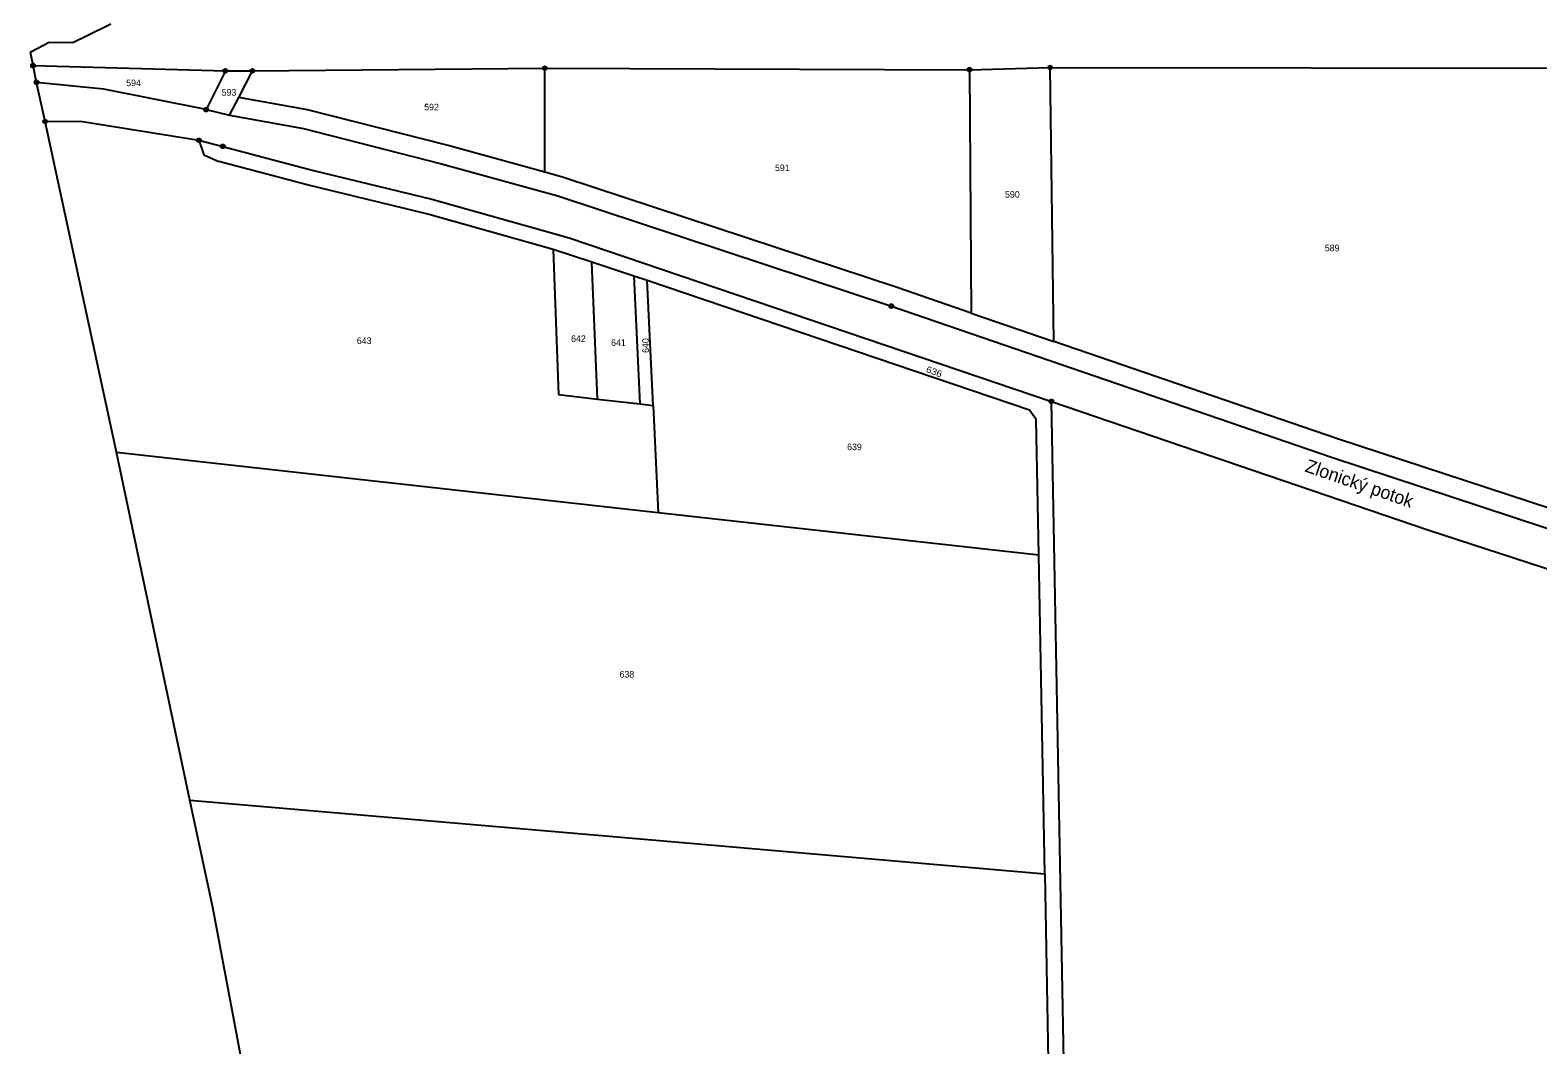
# Model space of a CAD drawing. Extents: x -759947 to -757003, y -1019641 to -1017100.
# Drawn here: x -759814.7 to -759425.7, y -1018690.8 to -1018428.9 of the extents above; entities that cross this region are included whole.
import ezdxf
from ezdxf.enums import TextEntityAlignment as Align

# ---------------------------------------------------------------- set-up
doc = ezdxf.new("R2010")
doc.units = 0
doc.header["$LTSCALE"] = 0.68
for name, color, linetype, lineweight in [('1', 7, 'Continuous', 25), ('7', 7, 'Continuous', 13), ('8', 7, 'Continuous', 25)]:
    doc.layers.add(name, color=color, linetype=linetype, lineweight=lineweight)
doc.layers.add('2', color=7, linetype='Continuous')

msp = doc.modelspace()

# ---------------------------------------------------------------- linework, layer by layer
at = {"layer": '1'}
for p, q in [((-759793.9, -1018427.43), (-759800.17, -1018430.47)), ((-759800.17, -1018430.47), (-759803.53, -1018432.1)), ((-759814.67, -1018434.67), (-759809.76, -1018432.02)), ((-759814.67, -1018434.67), (-759814.33, -1018436.27)), ((-759809.76, -1018432.02), (-759803.53, -1018432.1)), ((-759814.33, -1018436.27), (-759813.93, -1018438.11)), ((-759813, -1018442.42), (-759813.93, -1018438.11)), ((-759813.93, -1018438.11), (-759764.32, -1018439.44)), ((-759757.31, -1018439.44), (-759681.89, -1018438.78)), ((-759681.87, -1018465.61), (-759681.89, -1018438.78)), ((-759681.89, -1018438.78), (-759572.38, -1018439.15)), ((-759572.38, -1018439.15), (-759551.55, -1018438.58)), ((-759572.38, -1018439.15), (-759571.91, -1018501.94)), ((-759551.55, -1018438.58), (-759411.68, -1018438.73)), ((-759550.6, -1018509.26), (-759551.55, -1018438.58)), ((-759810.81, -1018452.53), (-759813, -1018442.42)), ((-759795.64, -1018444.2), (-759813, -1018442.42)), ((-759764.32, -1018439.44), (-759769.26, -1018449.47)), ((-759764.32, -1018439.44), (-759757.31, -1018439.44)), ((-759760.88, -1018446.33), (-759757.31, -1018439.44)), ((-759769.26, -1018449.47), (-759795.64, -1018444.2)), ((-759763.23, -1018450.86), (-759760.88, -1018446.33)), ((-759743.12, -1018449.48), (-759760.88, -1018446.33)), ((-759769.26, -1018449.47), (-759763.23, -1018450.86)), ((-759763.23, -1018450.86), (-759744.18, -1018454.37)), ((-759707.22, -1018458.63), (-759743.12, -1018449.48)), ((-759810.81, -1018452.53), (-759801.71, -1018452.43)), ((-759801.71, -1018452.43), (-759771.16, -1018457.37)), ((-759744.18, -1018454.37), (-759708.54, -1018463.45)), ((-759771.16, -1018457.37), (-759769.9, -1018461.15)), ((-759771.16, -1018457.37), (-759764.97, -1018458.94)), ((-759681.87, -1018465.61), (-759707.22, -1018458.63)), ((-759769.9, -1018461.15), (-759766.04, -1018462.81)), ((-759764.97, -1018458.94), (-759741.54, -1018465.18)), ((-759743.24, -1018468.83), (-759766.04, -1018462.81)), ((-759741.54, -1018465.18), (-759711.07, -1018472.56)), ((-759708.54, -1018463.45), (-759678.52, -1018471.72)), ((-759677.06, -1018466.94), (-759681.87, -1018465.61)), ((-759712.07, -1018476.43), (-759743.24, -1018468.83)), ((-759590.98, -1018495.39), (-759677.06, -1018466.94)), ((-759711.07, -1018472.56), (-759675.65, -1018482.55)), ((-759678.52, -1018471.72), (-759592.51, -1018500.15)), ((-759679.79, -1018485.53), (-759712.07, -1018476.43)), ((-759679.79, -1018485.53), (-759678.36, -1018523)), ((-759669.76, -1018488.84), (-759679.79, -1018485.53)), ((-759675.65, -1018482.55), (-759551.22, -1018524.74)), ((-759658.96, -1018492.41), (-759669.76, -1018488.84)), ((-759668.28, -1018524.15), (-759669.76, -1018488.84)), ((-759655.46, -1018493.56), (-759658.96, -1018492.41)), ((-759658.96, -1018492.41), (-759657.42, -1018525.39)), ((-759653.96, -1018525.78), (-759655.46, -1018493.56)), ((-759556.9, -1018527), (-759655.46, -1018493.56)), ((-759571.91, -1018501.94), (-759590.98, -1018495.39)), ((-759592.51, -1018500.15), (-759478.96, -1018539.15)), ((-759571.91, -1018501.94), (-759550.6, -1018509.26)), ((-759477.4, -1018534.4), (-759550.6, -1018509.26)), ((-759678.36, -1018523), (-759668.28, -1018524.15)), ((-759668.28, -1018524.15), (-759657.42, -1018525.39)), ((-759551.22, -1018524.74), (-759454.11, -1018557.92)), ((-759549.17, -1018634.98), (-759551.22, -1018524.74)), ((-759657.42, -1018525.39), (-759653.96, -1018525.78)), ((-759653.96, -1018525.78), (-759652.68, -1018553.4)), ((-759555.14, -1018529.42), (-759556.9, -1018527)), ((-759554.49, -1018564.34), (-759555.14, -1018529.42)), ((-759411.67, -1018556.04), (-759477.4, -1018534.4)), ((-759773.5, -1018627.63), (-759792.37, -1018537.83)), ((-759792.37, -1018537.83), (-759652.68, -1018553.4)), ((-759478.96, -1018539.15), (-759325.74, -1018589.59)), ((-759652.68, -1018553.4), (-759554.49, -1018564.34)), ((-759454.11, -1018557.92), (-759302.12, -1018607.5)), ((-759552.95, -1018646.65), (-759554.49, -1018564.34)), ((-759767.54, -1018655.35), (-759773.5, -1018627.63)), ((-759773.5, -1018627.63), (-759663.23, -1018637.14)), ((-759663.23, -1018637.14), (-759552.95, -1018646.65)), ((-759547.11, -1018745.22), (-759549.17, -1018634.98)), ((-759552.95, -1018646.65), (-759551.04, -1018749.13)), ((-759738.4, -1018809.93), (-759767.54, -1018655.35))]:
    msp.add_line(p, q, dxfattribs=at)
msp.add_lwpolyline([(-759792.37, -1018537.83), (-759809.09, -1018460.5), (-759810.81, -1018452.53)], dxfattribs=at)
at = {"layer": '8'}
for centre, radius in [((-759813.93, -1018438.1099), 0.5), ((-759813.93, -1018438.1099), 0.0303), ((-759764.32, -1018439.4399), 0.5), ((-759757.31, -1018439.4399), 0.5), ((-759681.89, -1018438.7799), 0.5), ((-759681.89, -1018438.7799), 0.0303), ((-759572.38, -1018439.1499), 0.5), ((-759572.38, -1018439.1499), 0.0303), ((-759551.55, -1018438.5799), 0.5), ((-759551.55, -1018438.5799), 0.0303), ((-759813, -1018442.4199), 0.5), ((-759813, -1018442.4199), 0.0303), ((-759764.32, -1018439.4399), 0.0303), ((-759757.31, -1018439.4399), 0.0303), ((-759769.26, -1018449.4699), 0.5), ((-759769.26, -1018449.4699), 0.0303), ((-759810.81, -1018452.5299), 0.5), ((-759810.81, -1018452.5299), 0.0303), ((-759771.16, -1018457.3699), 0.5), ((-759771.16, -1018457.3699), 0.0303), ((-759764.97, -1018458.9399), 0.5), ((-759764.97, -1018458.9399), 0.0303), ((-759592.51, -1018500.1499), 0.5), ((-759592.51, -1018500.1499), 0.0303), ((-759551.22, -1018524.7399), 0.5), ((-759551.22, -1018524.7399), 0.0303)]:
    msp.add_circle(centre, radius, dxfattribs=at)

# ---------------------------------------------------------------- texts
at = {"layer": '2'}
for s, p in [('594', (-759789.9, -1018443.405)), ('593', (-759765.27, -1018445.865)), ('592', (-759713.03, -1018449.655)), ('591', (-759622.54, -1018465.325)), ('590', (-759563.19, -1018472.185)), ('589', (-759480.69, -1018486.025)), ('643', (-759730.41, -1018509.945)), ('642', (-759675.13, -1018509.395)), ('641', (-759664.81, -1018510.435)), ('639', (-759603.92, -1018537.335)), ('638', (-759662.64, -1018596.025))]:
    msp.add_text(s, height=1.7, dxfattribs=at).set_placement(p)
msp.add_text('640', height=1.7, rotation=91, dxfattribs=at).set_placement((-759655.025, -1018512.232))
at = {"layer": '2', "width": 1.1}
msp.add_text('636', height=1.7, rotation=339, dxfattribs=at).set_placement((-759583.732, -1018517.136))
at = {"layer": '7'}
msp.add_text('Zlonický potok', height=3.4, rotation=341, dxfattribs=at).set_placement((-759472.305, -1018547.5204), align=Align.CENTER)

doc.saveas('drawing.dxf')
